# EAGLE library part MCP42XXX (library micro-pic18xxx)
Dual digital potentiometer with SPI interface
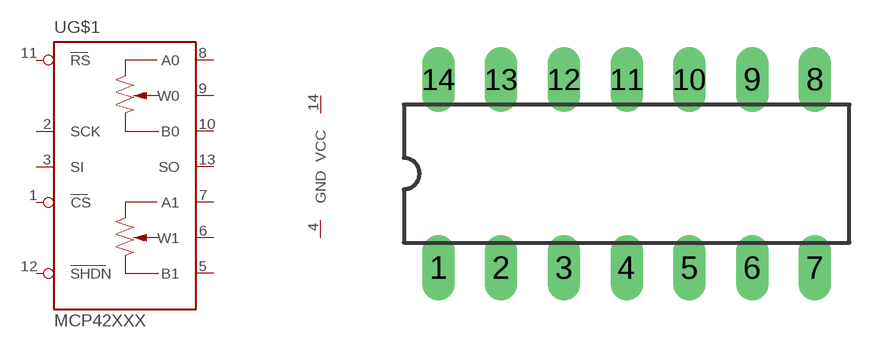
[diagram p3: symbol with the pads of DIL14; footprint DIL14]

Designator prefix -; gates G$1=MCP42XX VCC=VDD GND=VSS

## MCP42XXXP  [DIL14]
1  G$1:CS  in
2  G$1:SCK  in
3  G$1:SI  in
4  GND:GND  pwr
5  G$1:B1  pas
6  G$1:W1  pas
7  G$1:A1  pas
8  G$1:A0  pas
9  G$1:W0  pas
10  G$1:B0  pas
11  G$1:RS  in
12  G$1:SHDN  in
13  G$1:SO  out
14  VCC:VCC  pwr

## Footprint DIL14 (pad centres in mm)
Dual In Line
drill 0.813 long: 1 -7.62,-3.81; 2 -5.08,-3.81; 3 -2.54,-3.81; 4 0,-3.81; 5 2.54,-3.81; 6 5.08,-3.81; 7 7.62,-3.81; 8 7.62,3.81; 9 5.08,3.81; 10 2.54,3.81; 11 0,3.81; 12 -2.54,3.81; 13 -5.08,3.81; 14 -7.62,3.81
